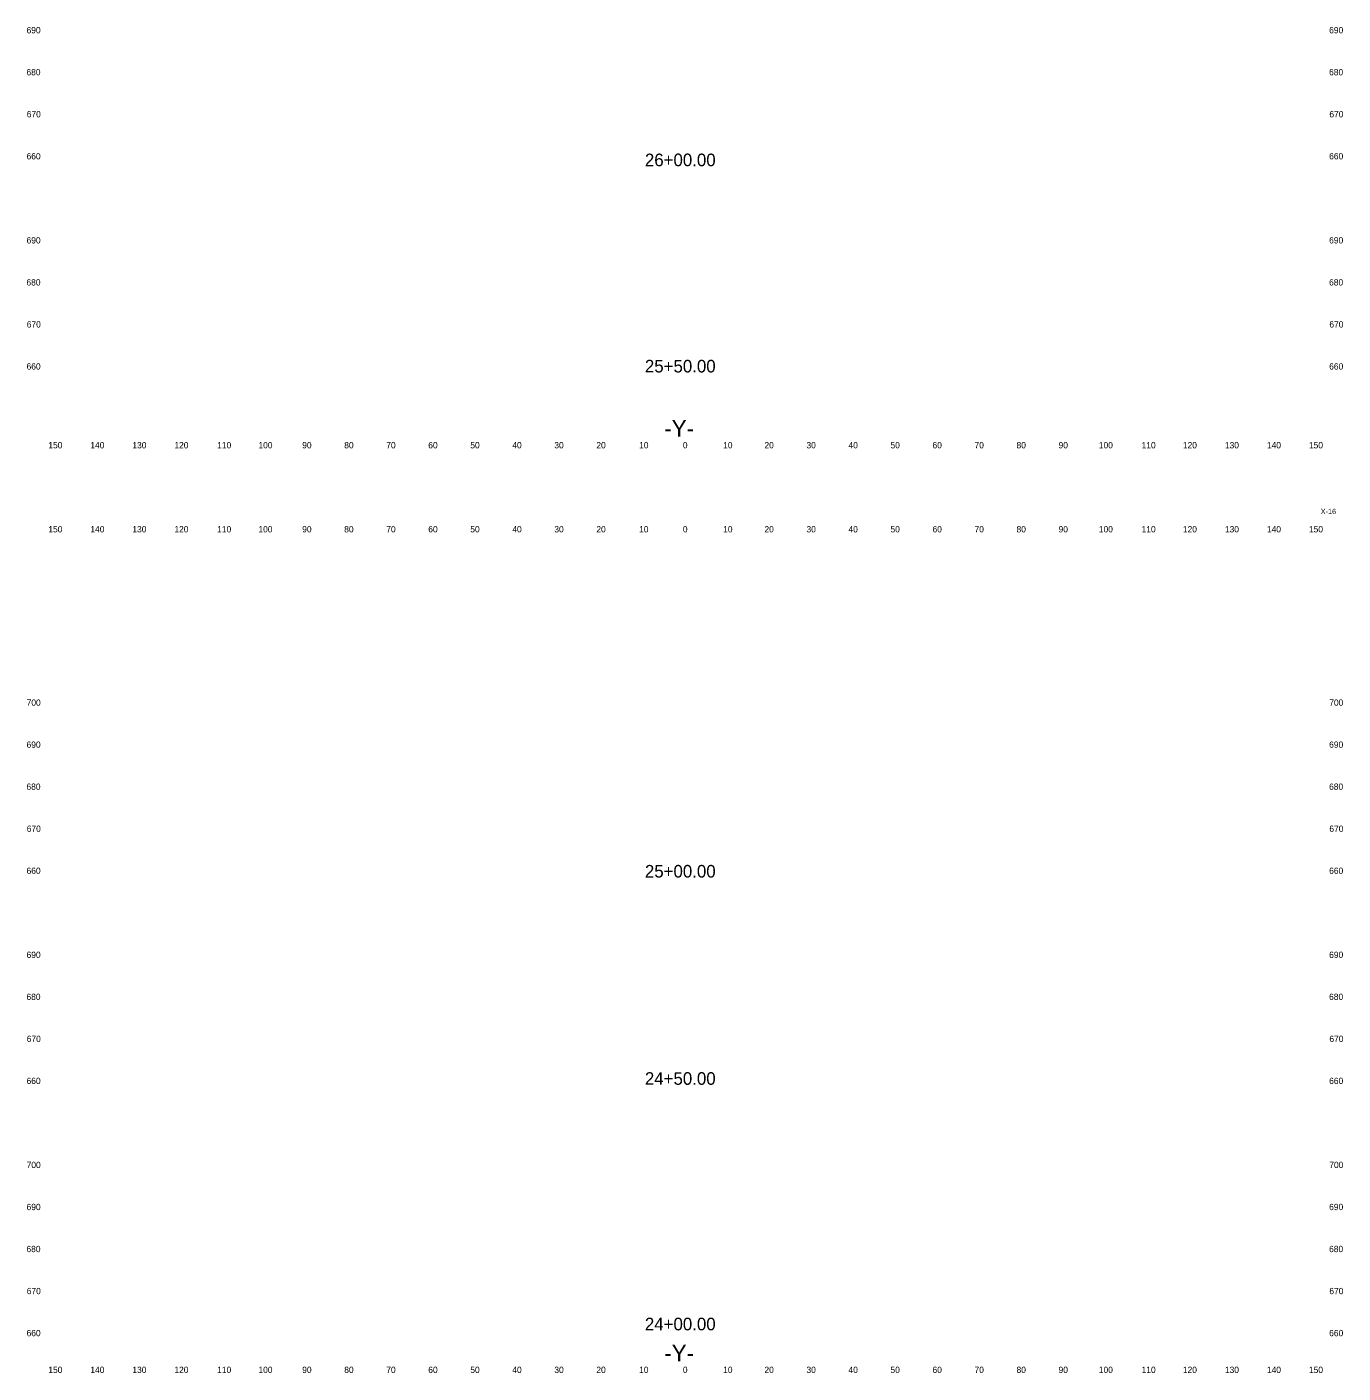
# Model space of a CAD drawing. Extents: x 3 to 317, y 1 to 1307.
# Drawn here: x 3.3 to 316.6, y 661.2 to 981.5 of the extents above; entities that cross this region are included whole.
import ezdxf

# ---------------------------------------------------------------- set-up
doc = ezdxf.new("R2010")
doc.units = 0
for name, color, linetype in [('Prop XS Alignment Label', 7, 'Continuous'), ('Prop XS Elevation Labels', 7, 'Continuous'), ('Prop XS Offset Labels', 7, 'Continuous'), ('Prop XS Sheet Number', 7, 'Continuous'), ('Prop XS Station Labels', 7, 'Continuous')]:
    doc.layers.add(name, color=color, linetype=linetype)

msp = doc.modelspace()

# ---------------------------------------------------------------- texts
at = {"layer": 'Prop XS Alignment Label'}
for p in [(155, 884), (155, 664)]:
    msp.add_text('-Y-', height=4, dxfattribs=at).set_placement(p)
at = {"layer": 'Prop XS Elevation Labels'}
for s, p in [('690', (3.26, 980)), ('690', (313.26, 980)), ('680', (3.24, 970)), ('680', (313.24, 970)), ('670', (3.3, 960)), ('670', (313.3, 960)), ('660', (3.26, 950)), ('660', (313.26, 950)), ('690', (3.26, 930)), ('690', (313.26, 930)), ('680', (3.24, 920)), ('680', (313.24, 920)), ('670', (3.3, 910)), ('670', (313.3, 910)), ('660', (3.26, 900)), ('660', (313.26, 900)), ('700', (3.28, 820)), ('700', (313.28, 820)), ('690', (3.26, 810)), ('690', (313.26, 810)), ('680', (3.24, 800)), ('680', (313.24, 800)), ('670', (3.3, 790)), ('670', (313.3, 790)), ('660', (3.26, 780)), ('660', (313.26, 780)), ('690', (3.26, 760)), ('690', (313.26, 760)), ('680', (3.24, 750)), ('680', (313.24, 750)), ('670', (3.3, 740)), ('670', (313.3, 740)), ('660', (3.26, 730)), ('660', (313.26, 730)), ('700', (3.28, 710)), ('700', (313.28, 710)), ('690', (3.26, 700)), ('690', (313.26, 700)), ('680', (3.24, 690)), ('680', (313.24, 690)), ('670', (3.3, 680)), ('670', (313.3, 680)), ('660', (3.26, 670)), ('660', (313.26, 670))]:
    msp.add_text(s, height=1.5, dxfattribs=at).set_placement(p)
at = {"layer": 'Prop XS Offset Labels'}
for s, p in [('150', (8.44, 881.25)), ('140', (18.44, 881.25)), ('130', (28.44, 881.25)), ('120', (38.44, 881.25)), ('110', (48.62, 881.25)), ('100', (58.44, 881.25)), ('90', (68.86, 881.25)), ('80', (78.86, 881.25)), ('70', (88.86, 881.25)), ('60', (98.86, 881.25)), ('50', (108.86, 881.25)), ('40', (118.86, 881.25)), ('30', (128.86, 881.25)), ('20', (138.86, 881.25)), ('10', (149.04, 881.25)), ('0', (159.45, 881.25)), ('10', (169.04, 881.25)), ('20', (178.86, 881.25)), ('30', (188.86, 881.25)), ('40', (198.86, 881.25)), ('50', (208.86, 881.25)), ('60', (218.86, 881.25)), ('70', (228.86, 881.25)), ('80', (238.86, 881.25)), ('90', (248.86, 881.25)), ('100', (258.44, 881.25)), ('110', (268.62, 881.25)), ('120', (278.44, 881.25)), ('130', (288.44, 881.25)), ('140', (298.44, 881.25)), ('150', (308.44, 881.25)), ('150', (8.44, 861.25)), ('140', (18.44, 861.25)), ('130', (28.44, 861.25)), ('120', (38.44, 861.25)), ('110', (48.62, 861.25)), ('100', (58.44, 861.25)), ('90', (68.86, 861.25)), ('80', (78.86, 861.25)), ('70', (88.86, 861.25)), ('60', (98.86, 861.25)), ('50', (108.86, 861.25)), ('40', (118.86, 861.25)), ('30', (128.86, 861.25)), ('20', (138.86, 861.25)), ('10', (149.04, 861.25)), ('0', (159.45, 861.25)), ('10', (169.04, 861.25)), ('20', (178.86, 861.25)), ('30', (188.86, 861.25)), ('40', (198.86, 861.25)), ('50', (208.86, 861.25)), ('60', (218.86, 861.25)), ('70', (228.86, 861.25)), ('80', (238.86, 861.25)), ('90', (248.86, 861.25)), ('100', (258.44, 861.25)), ('110', (268.62, 861.25)), ('120', (278.44, 861.25)), ('130', (288.44, 861.25)), ('140', (298.44, 861.25)), ('150', (308.44, 861.25)), ('150', (8.44, 661.25)), ('140', (18.44, 661.25)), ('130', (28.44, 661.25)), ('120', (38.44, 661.25)), ('110', (48.62, 661.25)), ('100', (58.44, 661.25)), ('90', (68.86, 661.25)), ('80', (78.86, 661.25)), ('70', (88.86, 661.25)), ('60', (98.86, 661.25)), ('50', (108.86, 661.25)), ('40', (118.86, 661.25)), ('30', (128.86, 661.25)), ('20', (138.86, 661.25)), ('10', (149.04, 661.25)), ('0', (159.45, 661.25)), ('10', (169.04, 661.25)), ('20', (178.86, 661.25)), ('30', (188.86, 661.25)), ('40', (198.86, 661.25)), ('50', (208.86, 661.25)), ('60', (218.86, 661.25)), ('70', (228.86, 661.25)), ('80', (238.86, 661.25)), ('90', (248.86, 661.25)), ('100', (258.44, 661.25)), ('110', (268.62, 661.25)), ('120', (278.44, 661.25)), ('130', (288.44, 661.25)), ('140', (298.44, 661.25)), ('150', (308.44, 661.25))]:
    msp.add_text(s, height=1.5, dxfattribs=at).set_placement(p)
at = {"layer": 'Prop XS Sheet Number'}
msp.add_text('X-16', height=1.25, dxfattribs=at).set_placement((311.26, 865.62))
at = {"layer": 'Prop XS Station Labels'}
for s, p in [('26+00.00', (150.41, 948.38)), ('25+50.00', (150.41, 899.31)), ('25+00.00', (150.41, 779.13)), ('24+50.00', (150.41, 729.82)), ('24+00.00', (150.41, 671.4))]:
    msp.add_text(s, height=3, dxfattribs=at).set_placement(p)

doc.saveas('drawing.dxf')
